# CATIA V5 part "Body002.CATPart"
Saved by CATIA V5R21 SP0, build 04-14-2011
Part number: Body002
Definition: design
Nomenclature: Body002
Source: Unknown
Bounding box of the stored display mesh (mm): x -7.5 to 7.5, y -8.826 to 8, z -0.1 to 0
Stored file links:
  C:\Users\beatr\OneDrive\Documents\UNB\2026_1\Pi1\Componentes eletronicos\Encoder\Body002.CATPart
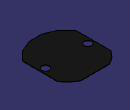
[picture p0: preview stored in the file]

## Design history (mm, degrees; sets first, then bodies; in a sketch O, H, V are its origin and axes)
Body1 "MANIFOLD_SOLID_BREP #2215" (main body)
  Solid1: solid without history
